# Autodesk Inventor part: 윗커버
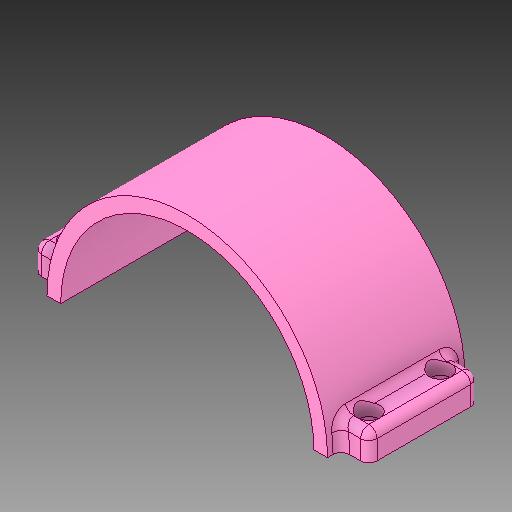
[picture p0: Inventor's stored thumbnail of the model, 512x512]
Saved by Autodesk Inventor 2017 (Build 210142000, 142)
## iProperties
Created: 2024-08
Part Number: 윗커버
Material: 일반
Document SubType Name: Modeling
Designer: MRC
Density: 1 g/cm^3
Appearance: 기본값
Author: jhkim
Sending System: Autodesk Inventor 2025
Preprocessor: ST-DEVELOPER v20
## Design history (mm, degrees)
feature "솔리드1"
node "솔리드2"
